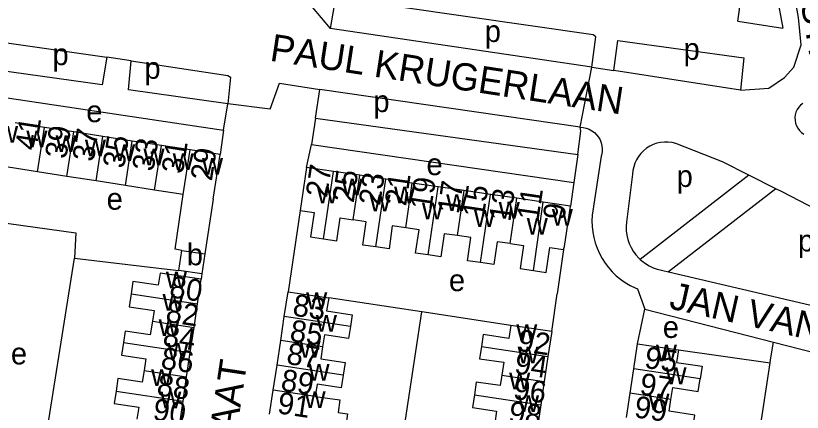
# Model space of a CAD drawing. Extents: x 163012 to 165277, y 382513 to 383987.
# Drawn here: x 163589 to 163733.4, y 383344.9 to 383417.8 of the extents above; entities that cross this region are included whole.
import ezdxf

# ---------------------------------------------------------------- set-up
doc = ezdxf.new("R2010")
doc.units = 0
for name, color, linetype in [('BLT_Basislijn', 7, 'Continuous'), ('BLT_Bebouwing', 7, 'Continuous'), ('BLT_Centroide', 7, 'Continuous'), ('BLT_Huisnummer', 7, 'Continuous'), ('BLT_Huisnummer_ tussenligend', 7, 'Continuous'), ('BLT_Onderverdeling_panden', 7, 'Continuous'), ('BLT_Straatnaam', 7, 'Continuous'), ('BLT_Vlakafsluiter', 7, 'Continuous')]:
    doc.layers.add(name, color=color, linetype=linetype)

msp = doc.modelspace()

# ---------------------------------------------------------------- linework, layer by layer
at = {"layer": 'BLT_Basislijn'}
for p, q in [((163726.59, 383433.78), (163729.84, 383415.57)), ((163721.6, 383416.84), (163723.02, 383427.4)), ((163721.6, 383416.84), (163729.84, 383415.57)), ((163694.79, 383408.36), (163646.74, 383415.51)), ((163580.33, 383413.88), (163605.73, 383410.21)), ((163610.19, 383409.55), (163605.73, 383410.21)), ((163694.79, 383408.36), (163698.82, 383407.74)), ((163722.07, 383404.16), (163698.82, 383407.74)), ((163637.46, 383405.43), (163644.86, 383404.27)), ((163644.07, 383399.01), (163644.86, 383404.27)), ((163692.64, 383397.33), (163644.86, 383404.27)), ((163627.18, 383396.81), (163627.95, 383401.66)), ((163635.76, 383400.65), (163627.95, 383401.66)), ((163644.07, 383399.01), (163643.3, 383394.15)), ((163644.07, 383399.01), (163692.22, 383392.32)), ((163627.18, 383396.81), (163626.54, 383392.29)), ((163642.38, 383389.93), (163643.3, 383394.15)), ((163643.3, 383394.15), (163691.48, 383387.2)), ((163692.22, 383392.32), (163691.48, 383387.2)), ((163696.51, 383392.04), (163694.85, 383381.17)), ((163702.27, 383388.71), (163701.14, 383379.9)), ((163723.61, 383388.53), (163703.66, 383373.03)), ((163728.55, 383386.03), (163723.61, 383388.53)), ((163691.48, 383387.2), (163690.85, 383382.83)), ((163728.55, 383386.03), (163708.86, 383370.73)), ((163641.23, 383382.03), (163639.02, 383367.1)), ((163689.61, 383374.85), (163688.43, 383366.69)), ((163707.81, 383370.98), (163708.86, 383370.73)), ((163623.2, 383370.35), (163623.08, 383369.39)), ((163708.86, 383370.73), (163751.18, 383360.78)), ((163687.43, 383359.78), (163688.43, 383366.69)), ((163703.2, 383367.6), (163704.53, 383363.87)), ((163663.58, 383363.38), (163646.52, 383365.97)), ((163703.2, 383357.52), (163704.53, 383363.87)), ((163704.53, 383363.87), (163728.13, 383357.8)), ((163654.69, 383304.83), (163663.58, 383363.38)), ((163679.89, 383360.91), (163663.58, 383363.38)), ((163728.13, 383357.8), (163736.01, 383355.77)), ((163710.69, 383356.4), (163727.51, 383354.03)), ((163724.92, 383336.65), (163727.51, 383354.03))]:
    msp.add_line(p, q, dxfattribs=at)
for points in [[(163647.78, 383449.29), (163643.45, 383419.42), (163646.74, 383415.51)], [(163722.07, 383404.16), (163727.29, 383404.5), (163730.14, 383406.46), (163731.9, 383408.4), (163733.23, 383412.47), (163732.72, 383417.5), (163729.72, 383434.26)], [(163694.79, 383408.36), (163695.51, 383413.95), (163695.03, 383414.32), (163647.72, 383421.19), (163646.74, 383415.51)], [(163605.73, 383410.21), (163604.9, 383405.14), (163579.87, 383408.64), (163580.33, 383413.88)], [(163698.82, 383407.74), (163699.56, 383413.27), (163722.67, 383410.08), (163722.07, 383404.16)], [(163627.95, 383401.66), (163609.7, 383404.21), (163610.19, 383409.55)], [(163610.19, 383409.55), (163627.99, 383406.82), (163628.47, 383406.54), (163627.95, 383401.66)], [(163578.16, 383399.8), (163578.81, 383404.02), (163627.18, 383396.81)], [(163733.52, 383401.72), (163733.12, 383401.39), (163732.77, 383401.01), (163732.49, 383400.58), (163732.27, 383400.11), (163732.13, 383399.62), (163732.07, 383399.11), (163732.09, 383398.59), (163732.18, 383398.08), (163732.36, 383397.6), (163732.6, 383397.14), (163732.92, 383396.73), (163733.29, 383396.37), (163733.71, 383396.08)], [(163692.22, 383392.32), (163692.8, 383396.6), (163692.64, 383397.33)], [(163692.64, 383397.33), (163693.21, 383397.29), (163693.77, 383397.16), (163694.3, 383396.97), (163694.81, 383396.69), (163695.27, 383396.35), (163695.67, 383395.95), (163696.02, 383395.5), (163696.3, 383395.01), (163696.51, 383394.47), (163696.64, 383393.92), (163696.69, 383393.35), (163696.67, 383392.78), (163696.56, 383392.22), (163696.51, 383392.04)], [(163710.2, 383394.36), (163709.51, 383394.52), (163708.82, 383394.6), (163708.11, 383394.61), (163707.42, 383394.53), (163706.73, 383394.38), (163706.07, 383394.14), (163705.44, 383393.84), (163704.84, 383393.46), (163704.3, 383393.02), (163703.8, 383392.52), (163703.37, 383391.97), (163703, 383391.37), (163702.71, 383390.74), (163702.48, 383390.07), (163702.34, 383389.38), (163702.27, 383388.71)], [(163723.61, 383388.53), (163718.76, 383390.97), (163710.2, 383394.36)], [(163739.43, 383380.3), (163737.62, 383381.37), (163729.72, 383385.44), (163728.55, 383386.03)], [(163575.3, 383381.36), (163585.09, 383380), (163600.04, 383377.94), (163599.84, 383373.27)], [(163694.85, 383381.17), (163694.81, 383380.13), (163694.84, 383379.1), (163694.95, 383378.07), (163695.14, 383377.05), (163695.41, 383376.05), (163695.75, 383375.08), (163696.17, 383374.13), (163696.66, 383373.22), (163697.22, 383372.35), (163697.85, 383371.52), (163698.54, 383370.75), (163699.28, 383370.03), (163700.08, 383369.37), (163700.93, 383368.78), (163701.82, 383368.25), (163702.74, 383367.79), (163703.2, 383367.6)], [(163701.14, 383379.9), (163701.08, 383379.1), (163701.11, 383378.3), (163701.21, 383377.5), (163701.39, 383376.72), (163701.65, 383375.96), (163701.98, 383375.23), (163702.38, 383374.54), (163702.86, 383373.89), (163703.39, 383373.29), (163703.66, 383373.03)], [(163593.55, 383333.89), (163593.61, 383334.29), (163599.84, 383373.27)], [(163599.84, 383373.27), (163615.77, 383371.34), (163618.97, 383370.99)], [(163703.66, 383373.03), (163703.98, 383372.74), (163704.62, 383372.26), (163705.31, 383371.84), (163706.03, 383371.49), (163706.78, 383371.22), (163707.56, 383371.03), (163707.81, 383370.98)], [(163727.51, 383354.03), (163727.59, 383354.55), (163728.13, 383357.8)]]:
    msp.add_lwpolyline(points, dxfattribs=at)
at = {"layer": 'BLT_Bebouwing'}
for p, q in [((163594.29, 383397.3), (163588.91, 383398.13)), ((163599.66, 383396.46), (163594.29, 383397.3)), ((163605.04, 383395.63), (163599.66, 383396.46)), ((163610.42, 383394.79), (163605.04, 383395.63)), ((163615.79, 383393.96), (163610.42, 383394.79)), ((163621.02, 383393.15), (163615.79, 383393.96)), ((163626.54, 383392.29), (163621.02, 383393.15)), ((163625.27, 383384.12), (163626.54, 383392.29)), ((163593.02, 383389.13), (163587.64, 383389.97)), ((163642.38, 383389.93), (163641.23, 383382.03)), ((163647.36, 383389.2), (163642.38, 383389.93)), ((163598.4, 383388.3), (163593.02, 383389.13)), ((163603.77, 383387.46), (163598.4, 383388.3)), ((163652.18, 383388.49), (163647.36, 383389.2)), ((163656.98, 383387.79), (163652.18, 383388.49)), ((163609.15, 383386.63), (163603.77, 383387.46)), ((163661.82, 383387.08), (163656.98, 383387.79)), ((163666.58, 383386.38), (163661.82, 383387.08)), ((163614.52, 383385.79), (163609.15, 383386.63)), ((163619.75, 383384.98), (163614.52, 383385.79)), ((163671.34, 383385.69), (163666.58, 383386.38)), ((163676.2, 383384.98), (163671.34, 383385.69)), ((163625.27, 383384.12), (163623.75, 383374.07)), ((163681.03, 383384.27), (163676.2, 383384.98)), ((163685.88, 383383.56), (163681.03, 383384.27)), ((163690.85, 383382.83), (163685.88, 383383.56)), ((163623.75, 383374.07), (163623.2, 383370.35)), ((163623.2, 383370.35), (163618.97, 383370.99)), ((163622.4, 383364.88), (163623.08, 383369.39)), ((163638.33, 383362.51), (163639.02, 383367.1)), ((163621.75, 383360.51), (163622.4, 383364.88)), ((163637.67, 383358.11), (163638.33, 383362.51)), ((163621.06, 383355.91), (163621.75, 383360.51)), ((163687.43, 383359.78), (163686.74, 383355.16)), ((163636.99, 383353.58), (163637.67, 383358.11)), ((163702.51, 383352.91), (163703.2, 383357.52)), ((163703.2, 383357.52), (163710.69, 383356.4)), ((163620.4, 383351.44), (163621.06, 383355.91)), ((163686.74, 383355.16), (163686.05, 383350.59)), ((163636.3, 383349.01), (163636.99, 383353.58)), ((163701.84, 383348.42), (163702.51, 383352.91)), ((163619.73, 383346.98), (163620.4, 383351.44)), ((163686.05, 383350.59), (163685.41, 383346.31)), ((163635.63, 383344.56), (163636.3, 383349.01)), ((163701.17, 383343.97), (163701.84, 383348.42)), ((163619.06, 383342.48), (163619.73, 383346.98)), ((163685.41, 383346.31), (163684.73, 383341.79))]:
    msp.add_line(p, q, dxfattribs=at)
for points in [[(163618.67, 383377.43), (163619.75, 383384.98)], [(163689.61, 383374.85), (163689.76, 383375.39), (163690.85, 383382.83)], [(163641.23, 383382.03), (163643.79, 383381.66), (163643.13, 383377.16), (163645.55, 383376.81)], [(163645.55, 383376.81), (163647.96, 383376.45), (163648.58, 383380.65), (163650.98, 383380.3)], [(163655.15, 383375.33), (163652.76, 383375.68), (163653.38, 383379.95), (163650.98, 383380.3)], [(163660.61, 383378.83), (163658.16, 383379.18), (163657.55, 383374.98), (163655.15, 383375.33)], [(163664.75, 383373.87), (163662.43, 383374.21), (163663.06, 383378.47), (163660.61, 383378.83)], [(163619.53, 383374.7), (163618.29, 383374.89), (163618.67, 383377.43)], [(163670.12, 383377.4), (163667.68, 383377.76), (163667.06, 383373.53), (163664.75, 383373.87)], [(163674.36, 383372.44), (163671.95, 383372.79), (163672.57, 383377.05), (163670.12, 383377.4)], [(163679.81, 383375.93), (163677.38, 383376.28), (163676.77, 383372.08), (163674.36, 383372.44)], [(163679.81, 383375.93), (163682.24, 383375.57), (163681.66, 383371.34), (163684.05, 383370.99)], [(163684.05, 383370.99), (163686.43, 383370.65), (163687.1, 383375.22), (163689.61, 383374.85)], [(163618.97, 383370.99), (163619.53, 383374.7)], [(163623.08, 383369.39), (163618.13, 383370.12), (163615.54, 383370.51), (163615.18, 383368.28), (163610.54, 383368.96), (163610.2, 383366.7)], [(163610.2, 383366.7), (163609.84, 383364.32), (163614.43, 383363.64), (163614.12, 383361.65)], [(163639.02, 383367.1), (163643.97, 383366.36), (163646.52, 383365.97)], [(163646.52, 383365.97), (163646.09, 383363.57), (163650.8, 383362.86), (163650.47, 383360.68)], [(163614.12, 383361.65), (163613.71, 383359.15), (163609.12, 383359.83), (163608.81, 383357.74)], [(163650.47, 383360.68), (163650.14, 383358.49), (163645.69, 383359.16), (163645.36, 383356.95)], [(163679.89, 383360.91), (163679.58, 383358.51), (163674.84, 383359.21), (163674.51, 383357)], [(163687.43, 383359.78), (163682.49, 383360.52), (163679.89, 383360.91)], [(163608.81, 383357.74), (163608.46, 383355.43), (163612.89, 383354.77), (163612.57, 383352.61)], [(163645.36, 383356.95), (163645.03, 383354.74), (163649.48, 383354.06), (163649.14, 383351.75)], [(163674.51, 383357), (163674.18, 383354.78), (163678.61, 383354.12), (163678.26, 383351.76)], [(163710.69, 383356.4), (163710.35, 383354.09), (163715.03, 383353.39), (163714.68, 383351.08)], [(163612.57, 383352.61), (163612.25, 383350.45), (163607.78, 383351.11), (163607.44, 383348.82)], [(163649.14, 383351.75), (163648.79, 383349.44), (163644.34, 383350.11), (163644, 383347.85)], [(163678.26, 383351.76), (163677.97, 383349.83), (163673.57, 383350.48), (163673.22, 383348.14)], [(163709.3, 383347.3), (163709.63, 383349.48), (163714.34, 383348.77), (163714.68, 383351.08)], [(163607.44, 383348.82), (163607.09, 383346.52), (163611.61, 383345.85), (163611.28, 383343.64)], [(163644, 383347.85), (163648.55, 383347.23), (163648.19, 383344.9), (163649.93, 383344.64), (163649.64, 383342.42), (163647.86, 383342.72)], [(163673.22, 383348.14), (163672.87, 383345.79), (163677.28, 383345.13), (163676.96, 383342.95)], [(163713.33, 383342.14), (163713.67, 383344.42), (163708.98, 383345.12), (163709.3, 383347.3)]]:
    msp.add_lwpolyline(points, dxfattribs=at)
at = {"layer": 'BLT_Onderverdeling_panden'}
for p, q in [((163593.02, 383389.13), (163594.29, 383397.3)), ((163598.4, 383388.3), (163599.66, 383396.46)), ((163603.77, 383387.46), (163605.04, 383395.63)), ((163609.15, 383386.63), (163610.42, 383394.79)), ((163614.52, 383385.79), (163615.79, 383393.96)), ((163619.75, 383384.98), (163621.02, 383393.15)), ((163645.55, 383376.81), (163647.36, 383389.2)), ((163650.98, 383380.3), (163652.18, 383388.49)), ((163655.15, 383375.33), (163656.98, 383387.79)), ((163660.61, 383378.83), (163661.82, 383387.08)), ((163664.75, 383373.87), (163666.58, 383386.38)), ((163670.12, 383377.4), (163671.34, 383385.69)), ((163674.36, 383372.44), (163676.2, 383384.98)), ((163679.81, 383375.93), (163681.03, 383384.27)), ((163684.05, 383370.99), (163685.88, 383383.56)), ((163619.53, 383374.7), (163623.75, 383374.07)), ((163610.2, 383366.7), (163622.4, 383364.88)), ((163650.47, 383360.68), (163638.33, 383362.51)), ((163614.12, 383361.65), (163621.75, 383360.51)), ((163645.36, 383356.95), (163637.67, 383358.11)), ((163608.81, 383357.74), (163621.06, 383355.91)), ((163674.51, 383357), (163686.74, 383355.16)), ((163649.14, 383351.75), (163636.99, 383353.58)), ((163612.57, 383352.61), (163620.4, 383351.44)), ((163714.68, 383351.08), (163702.51, 383352.91)), ((163678.26, 383351.76), (163686.05, 383350.59)), ((163607.44, 383348.82), (163619.73, 383346.98)), ((163644, 383347.85), (163636.3, 383349.01)), ((163673.22, 383348.14), (163685.41, 383346.31)), ((163709.3, 383347.3), (163701.84, 383348.42))]:
    msp.add_line(p, q, dxfattribs=at)
at = {"layer": 'BLT_Vlakafsluiter'}
for p, q in [((163692.64, 383397.33), (163694.79, 383408.36)), ((163635.76, 383400.65), (163637.46, 383405.43))]:
    msp.add_line(p, q, dxfattribs=at)

# ---------------------------------------------------------------- texts
at = {"layer": 'BLT_Centroide'}
for s, p in [('p', (163675.13, 383413)), ('p', (163711.63, 383409.72)), ('p', (163595.76, 383408.74)), ('p', (163612.64, 383406.23)), ('p', (163654.68, 383400.12)), ('e', (163601.97, 383398.26)), ('w', (163585.59, 383394.47)), ('w', (163590.97, 383393.62)), ('w', (163596.34, 383392.8)), ('w', (163601.72, 383391.97)), ('w', (163607.09, 383391.12)), ('w', (163612.47, 383390.3)), ('w', (163617.84, 383389.45)), ('w', (163623.22, 383388.62)), ('e', (163664.43, 383388.53)), ('p', (163710.36, 383386.35)), ('w', (163648.86, 383384.8)), ('e', (163605.71, 383382.17)), ('w', (163644.3, 383383.33)), ('w', (163658.48, 383383.34)), ('w', (163653.98, 383381.86)), ('w', (163668.05, 383381.94)), ('w', (163663.59, 383380.42)), ('w', (163677.69, 383380.5)), ('w', (163673.16, 383379.02)), ('w', (163687.45, 383379.25)), ('w', (163682.84, 383377.58)), ('p', (163732.63, 383374.49)), ('b', (163620.43, 383371.95)), ('w', (163616.59, 383367.69)), ('e', (163668.55, 383367.2)), ('w', (163615.98, 383363.59)), ('w', (163642.34, 383363.88)), ('w', (163644.12, 383359.72)), ('w', (163615.26, 383358.97)), ('w', (163680.91, 383358.03)), ('e', (163707.82, 383358.59)), ('w', (163641.12, 383354.94)), ('e', (163588.13, 383353.73)), ('w', (163616.86, 383354.59)), ('w', (163681.16, 383353.91)), ('w', (163706.55, 383354.31)), ('w', (163642.77, 383350.72)), ('w', (163613.87, 383349.78)), ('w', (163679.61, 383349.12)), ('w', (163708.31, 383350.09)), ('w', (163615.55, 383345.66)), ('w', (163642.05, 383345.72)), ('w', (163681.23, 383344.97)), ('w', (163705.18, 383345.28))]:
    msp.add_text(s, height=4, dxfattribs=at).set_placement(p)
at = {"layer": 'BLT_Huisnummer'}
for s, rotation, p in [('41', 81.1726, (163592.8, 383392.94)), ('37', 81.1716, (163603.33, 383390.87)), ('33', 81.1763, (163614.3, 383389.11)), ('29', 81.1748, (163625.02, 383387.32)), ('27', 81.6447, (163646.17, 383384.27)), ('21', 81.6835, (163660.68, 383382.72)), ('17', 81.6725, (163670.35, 383381.27)), ('13', 81.6577, (163679.82, 383379.85)), ('9', 81.6723, (163689.72, 383380.13)), ('80', 351.4883, (163617.09, 383366.11)), ('83', 351.4386, (163639.71, 383362.74)), ('84', 351.5104, (163615.86, 383357.17)), ('92', 351.4637, (163680.96, 383356.27)), ('87', 351.4379, (163638.58, 383353.83)), ('95', 351.4685, (163704.3, 383353.11)), ('88', 351.4984, (163614.76, 383348.09)), ('96', 351.4683, (163680.21, 383347.42)), ('91', 351.4353, (163636.9, 383344.76)), ('99', 351.467, (163702.42, 383344.03))]:
    msp.add_text(s, height=4, rotation=rotation, dxfattribs=at).set_placement(p)
at = {"layer": 'BLT_Huisnummer_ tussenligend'}
for s, rotation, p in [('39', 81.1716, (163598.29, 383391.4)), ('35', 81.1763, (163608.91, 383389.64)), ('31', 81.1748, (163619.7, 383388.64)), ('25', 81.6835, (163651.06, 383383.32)), ('23', 81.6835, (163655.92, 383382.8)), ('19', 81.6725, (163665.31, 383381.97)), ('15', 81.6577, (163674.96, 383380.54)), ('11', 81.6723, (163684.98, 383380)), ('82', 351.4883, (163616.4, 383361.58)), ('85', 351.4386, (163639.19, 383358.05)), ('86', 351.5104, (163615.51, 383352.99)), ('94', 351.4637, (163680.43, 383352.09)), ('89', 351.4379, (163637.54, 383348.96)), ('97', 351.4685, (163703.42, 383348.24)), ('90', 351.4984, (163614.05, 383343.57)), ('98', 351.4683, (163679.34, 383343.07))]:
    msp.add_text(s, height=4, rotation=rotation, dxfattribs=at).set_placement(p)
at = {"layer": 'BLT_Straatnaam'}
for s, rotation, p in [('RUSTENBURGSTRAAT', 279.1757, (163725.67, 383466.55)), ('PAUL KRUGERLAAN', 351.2966, (163635.52, 383409.58)), ('JAN VAN RIEBEECKLAAN', 347.4096, (163708.81, 383364.05)), ('JOHANNESBURGSTRAAT', 81.4629, (163619.34, 383272.95))]:
    msp.add_text(s, height=5, rotation=rotation, dxfattribs=at).set_placement(p)

doc.saveas('drawing.dxf')
